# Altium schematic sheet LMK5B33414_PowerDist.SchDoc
size C; Date: Not shown in title block; ApprovedBy: Not shown in title block; CheckedBy: Not shown in title block; Author: Not shown in title block; CompanyName: Not shown in title block; Engineer: Not shown in title block; Organization: Not shown in title block; Address1: Not shown in title block; Address2: Not shown in title block; Address3: Not shown in title block; Address4: Not shown in title block; DocumentNumber: 2; Revision: Use project parameter SCH_Rev; SheetNumber: 2; SheetTotal: 3; PageSetup: Record=PageOptions¦CenterHorizontal=True¦CenterVertical=True¦PrintScale=1.00¦XCorrection=1.00¦YCorrection=1.00¦PrintKind=0¦BorderSize=5000000¦LeftOffset=0¦BottomOffset=0¦Orientation=2¦PaperLength=1000¦PaperWidth=1000¦Scale=100¦PaperSource=15¦PrintQuality=600¦MediaType=1¦DitherType=10¦PaperKind=Letter¦PrintScaleMode=1
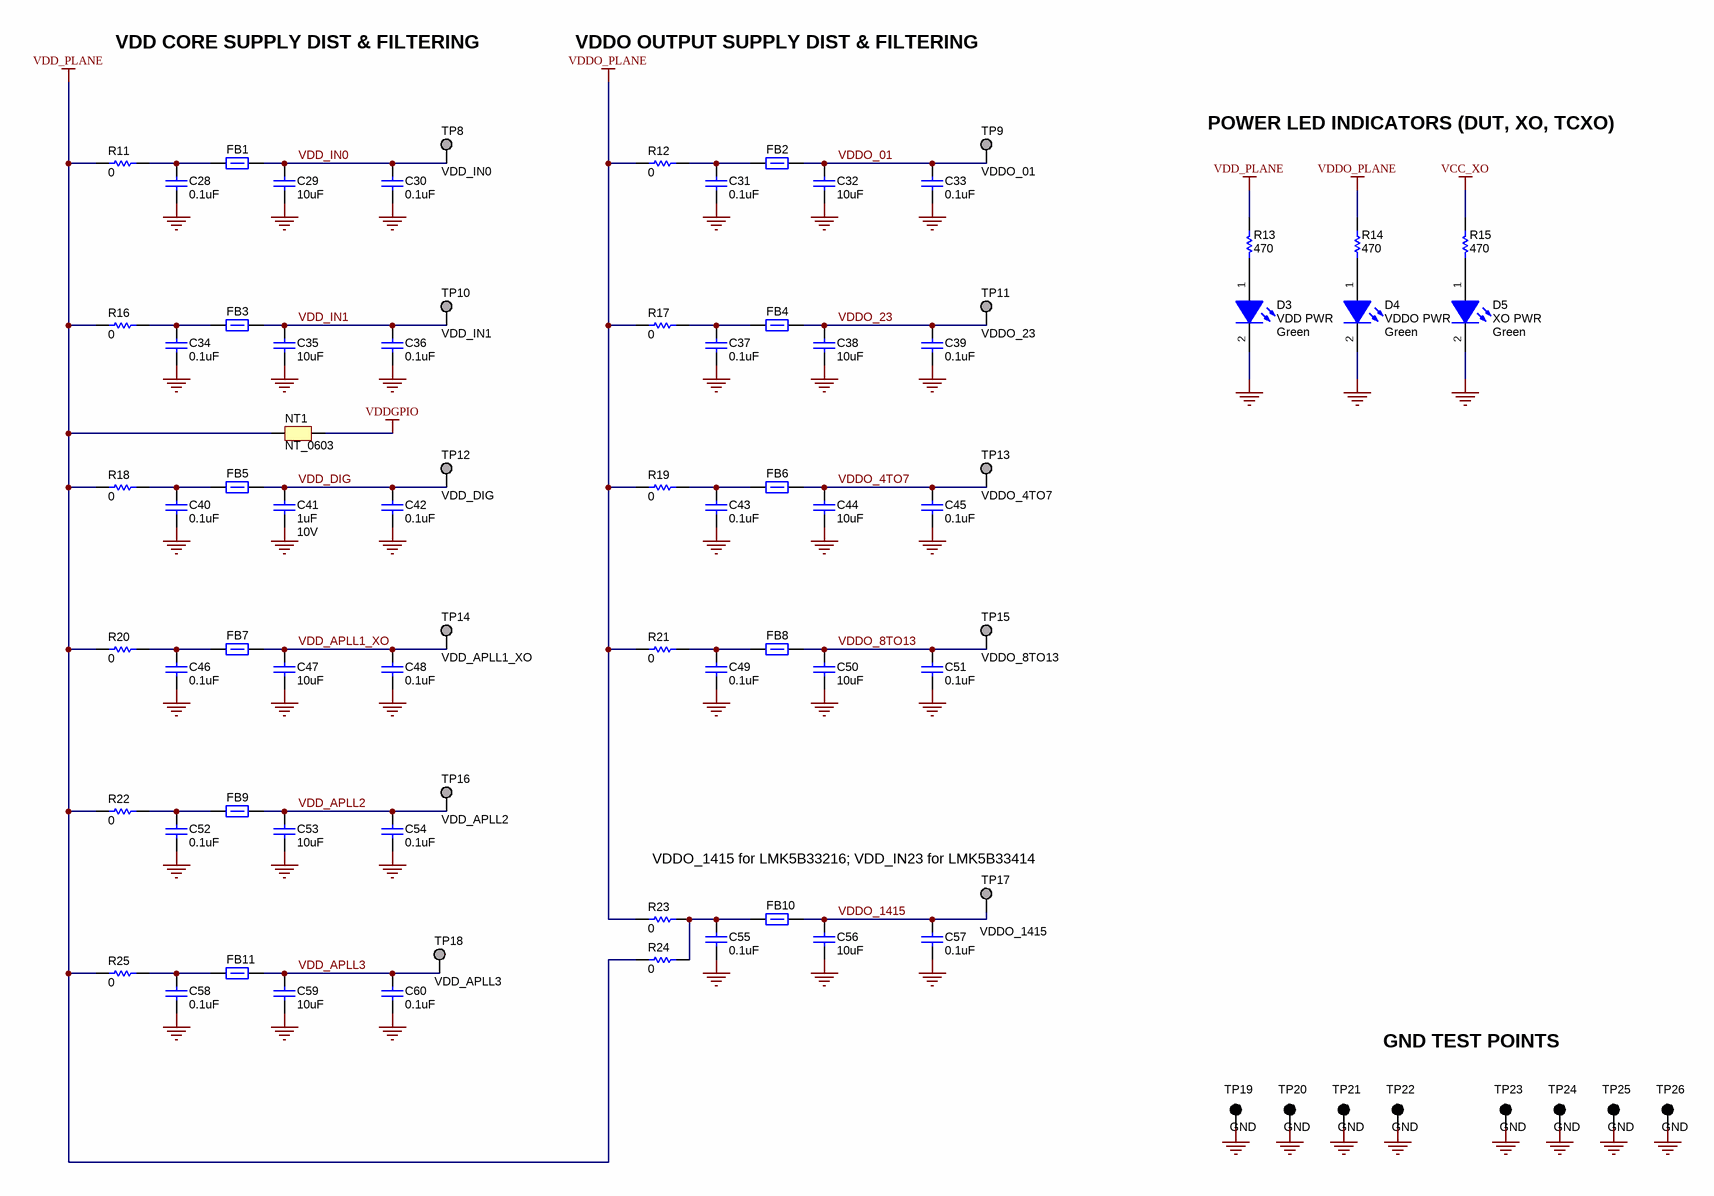
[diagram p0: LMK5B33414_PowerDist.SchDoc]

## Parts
C28  ValueDisplayed: 0.1uF  [0603L]  (hidden comment: Capacitor)
C29  ValueDisplayed: 10uF  [0603L]  (hidden comment: Capacitor)
C30  ValueDisplayed: 0.1uF  [0402L]  (hidden comment: Capacitor)
C31  ValueDisplayed: 0.1uF  [0603L]  (hidden comment: Capacitor)
C32  ValueDisplayed: 10uF  [0603L]  (hidden comment: Capacitor)
C33  ValueDisplayed: 0.1uF  [0402L]  (hidden comment: Capacitor)
C34  ValueDisplayed: 0.1uF  [0603L]  (hidden comment: Capacitor)
C35  ValueDisplayed: 10uF  [0603L]  (hidden comment: Capacitor)
C36  ValueDisplayed: 0.1uF  [0402L]  (hidden comment: Capacitor)
C37  ValueDisplayed: 0.1uF  [0603L]  (hidden comment: Capacitor)
C38  ValueDisplayed: 10uF  [0603L]  (hidden comment: Capacitor)
C39  ValueDisplayed: 0.1uF  [0402L]  (hidden comment: Capacitor)
C40  ValueDisplayed: 0.1uF  [0603L]  (hidden comment: Capacitor)
C41  ValueDisplayed: 1uF  VDC_V: 10V  [0603L]  (hidden comment: C0603C105K8PACTU)
C42  ValueDisplayed: 0.1uF  [0402L]  (hidden comment: Capacitor)
C43  ValueDisplayed: 0.1uF  [0603L]  (hidden comment: Capacitor)
C44  ValueDisplayed: 10uF  [0603L]  (hidden comment: Capacitor)
C45  ValueDisplayed: 0.1uF  [0402L]  (hidden comment: Capacitor)
C46  ValueDisplayed: 0.1uF  [0603L]  (hidden comment: Capacitor)
C47  ValueDisplayed: 10uF  [0603L]  (hidden comment: Capacitor)
C48  ValueDisplayed: 0.1uF  [0402L]  (hidden comment: Capacitor)
C49  ValueDisplayed: 0.1uF  [0603L]  (hidden comment: Capacitor)
C50  ValueDisplayed: 10uF  [0603L]  (hidden comment: Capacitor)
C51  ValueDisplayed: 0.1uF  [0402L]  (hidden comment: Capacitor)
C52  ValueDisplayed: 0.1uF  [0603L]  (hidden comment: Capacitor)
C53  ValueDisplayed: 10uF  [0603L]  (hidden comment: Capacitor)
C54  ValueDisplayed: 0.1uF  [0402L]  (hidden comment: Capacitor)
C55  ValueDisplayed: 0.1uF  [0603L]  (hidden comment: Capacitor)
C56  ValueDisplayed: 10uF  [0603L]  (hidden comment: Capacitor)
C57  ValueDisplayed: 0.1uF  [0402L]  (hidden comment: Capacitor)
C58  ValueDisplayed: 0.1uF  [0603L]  (hidden comment: Capacitor)
C59  ValueDisplayed: 10uF  [0603L]  (hidden comment: Capacitor)
C60  ValueDisplayed: 0.1uF  [0402L]  (hidden comment: Capacitor)
D3  VDD PWR  value Green  [LED_LTST-C190]
D4  VDDO PWR  value Green  [LED_LTST-C190]
D5  XO PWR  value Green  [LED_LTST-C190]
FB1  BLM18SG221TN1D  [0603L]  (value not drawn)
FB2  BLM18SG221TN1D  [0603L]  (value not drawn)
FB3  BLM18SG221TN1D  [0603L]  (value not drawn)
FB4  BLM18SG221TN1D  [0603L]  (value not drawn)
FB5  BLM18SG221TN1D  [0603L]  (value not drawn)
FB6  BLM18SG221TN1D  [0603L]  (value not drawn)
FB7  BLM18SG221TN1D  [0603L]  (value not drawn)
FB8  BLM18SG221TN1D  [0603L]  (value not drawn)
FB9  BLM18SG221TN1D  [0603L]  (value not drawn)
FB10  BLM18SG221TN1D  [0603L]  (value not drawn)
FB11  BLM18SG221TN1D  [0603L]  (value not drawn)
NT1  NT_0603  [NetTie_0603]  (net tie, no BOM)
R11  ValueDisplayed: 0  [0603]  (hidden comment: CRCW06030000Z0EA)
R12  ValueDisplayed: 0  [0603]  (hidden comment: CRCW06030000Z0EA)
R13  ValueDisplayed: 470  [0603]  (hidden comment: Resistor)
R14  ValueDisplayed: 470  [0603]  (hidden comment: Resistor)
R15  ValueDisplayed: 470  [0603]  (hidden comment: Resistor)
R16  ValueDisplayed: 0  [0603]  (hidden comment: CRCW06030000Z0EA)
R17  ValueDisplayed: 0  [0603]  (hidden comment: CRCW06030000Z0EA)
R18  ValueDisplayed: 0  [0603]  (hidden comment: CRCW06030000Z0EA)
R19  ValueDisplayed: 0  [0603]  (hidden comment: CRCW06030000Z0EA)
R20  ValueDisplayed: 0  [0603]  (hidden comment: CRCW06030000Z0EA)
R21  ValueDisplayed: 0  [0603]  (hidden comment: CRCW06030000Z0EA)
R22  ValueDisplayed: 0  [0603]  (hidden comment: CRCW06030000Z0EA)
R23  ValueDisplayed: 0  [0603]  (hidden comment: CRCW06030000Z0EA)
R24  ValueDisplayed: 0  [0603]  (hidden comment: CRCW06030000Z0EA)
R25  ValueDisplayed: 0  [0603]  (hidden comment: CRCW06030000Z0EA)
TP8  VDD_IN0  [TP_SM_1MM]  (no BOM)
TP9  VDDO_01  [TP_SM_1MM]  (no BOM)
TP10  VDD_IN1  [TP_SM_1MM]  (no BOM)
TP11  VDDO_23  [TP_SM_1MM]  (no BOM)
TP12  VDD_DIG  [TP_SM_1MM]  (no BOM)
TP13  VDDO_4TO7  [TP_SM_1MM]  (no BOM)
TP14  VDD_APLL1_XO  [TP_SM_1MM]  (no BOM)
TP15  VDDO_8TO13  [TP_SM_1MM]  (no BOM)
TP16  VDD_APLL2  [TP_SM_1MM]  (no BOM)
TP17  VDDO_1415  [TP_SM_1MM]  (no BOM)
TP18  VDD_APLL3  [TP_SM_1MM]  (no BOM)
TP19  GND  [Keystone5001]
TP20  GND  [Keystone5001]
TP21  GND  [Keystone5001]
TP22  GND  [Keystone5001]
TP23  GND  [Keystone5001]
TP24  GND  [Keystone5001]
TP25  GND  [Keystone5001]
TP26  GND  [Keystone5001]

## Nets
GND: C28.1 C29.2 C30.1 C31.1 C32.2 C33.1 C34.1 C35.2 C36.1 C37.1 C38.2 C39.1 C40.1 C41.2 C42.1 C43.1 C44.2 C45.1 C46.1 C47.2 C48.1 C49.1 C50.2 C51.1 C52.1 C53.2 C54.1 C55.1 C56.2 C57.1 C58.1 C59.2 C60.1 D3.2(K) D4.2(K) D5.2(K) TP19.1 TP20.1 TP21.1 TP22.1 TP23.1 TP24.1 TP25.1 TP26.1
VCC_XO: R15.1
VDD_PLANE: NT1.2 R11.2 R13.1 R16.2 R18.2 R20.2 R22.2 R24.1 R25.2
VDDGPIO: NT1.1
VDDO_PLANE: R12.2 R14.1 R17.2 R19.2 R21.2 R23.2
VDD_APLL1_XO: C47.1 C48.2 FB7.2 TP14.1
VDD_APLL2: C53.1 C54.2 FB9.2 TP16.1
VDD_APLL3: C59.1 C60.2 FB11.2 TP18.1
VDD_DIG: C41.1 C42.2 FB5.2 TP12.1
VDD_IN0: C29.1 C30.2 FB1.2 TP8.1
VDD_IN1: C35.1 C36.2 FB3.2 TP10.1
VDDO_01: C32.1 C33.2 FB2.2 TP9.1
VDDO_4TO7: C44.1 C45.2 FB6.2 TP13.1
VDDO_8TO13: C50.1 C51.2 FB8.2 TP15.1
VDDO_23: C38.1 C39.2 FB4.2 TP11.1
VDDO_1415: C56.1 C57.2 FB10.2 TP17.1
NetC28_2: C28.2 FB1.1 R11.1
NetC31_2: C31.2 FB2.1 R12.1
NetC34_2: C34.2 FB3.1 R16.1
NetC37_2: C37.2 FB4.1 R17.1
NetC40_2: C40.2 FB5.1 R18.1
NetC43_2: C43.2 FB6.1 R19.1
NetC46_2: C46.2 FB7.1 R20.1
NetC49_2: C49.2 FB8.1 R21.1
NetC52_2: C52.2 FB9.1 R22.1
NetC55_2: C55.2 FB10.1 R23.1 R24.2
NetC58_2: C58.2 FB11.1 R25.1
NetD3_1: D3.1(A) R13.2
NetD4_1: D4.1(A) R14.2
NetD5_1: D5.1(A) R15.2

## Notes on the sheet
- VDD CORE SUPPLY DIST & FILTERING
- VDDO OUTPUT SUPPLY DIST & FILTERING
- POWER LED INDICATORS (DUT, XO, TCXO)
- VDDO_1415 for LMK5B33216; VDD_IN23 for LMK5B33414
- GND TEST POINTS

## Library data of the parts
C28 C31 C34 C37 C40 C43 C46 C49 C52 C55 C58 = CMP-0006856-6: CAP, CERM, 0.1 uF, 25 V, +/- 5%, X7R, 0603; PartNumber: C0603C104J3RACTU; Manufacturer: Kemet; Polarized: N; Value: 0.1uF; U/M: EA; Cap_F: 100nF; Value1: Unknown; VDC_V: 25V; TaMin_C: -55°C; TaMax_C: 125°C; Cap_Case: 0603; AEC Category: Q200; SizeArea_mm2: 1.28; SizeAreaWB_mm2: 4.68; SizeX_mm: 1.6; SizeY_mm: 0.8; SizeZ_mm: 1
C29 C32 C35 C38 C44 C47 C50 C53 C56 C59 = CMP-0007003-5: CAP, CERM, 10 uF, 10 V, +/- 20%, X5R, 0603; PartNumber: C1608X5R1A106M080AC; Manufacturer: TDK; Polarized: N; Value: 10uF; U/M: EA; Cap_F: 10µF; ESR_ohm: 7.8m; Value1: 0.0078 ohm; VDC_V: 10V; IRMS_A: 1.85A; TaMin_C: -55°C; TaMax_C: 85°C; Cap_Case: 0603; SizeArea_mm2: 1.28; SizeAreaWB_mm2: 4.68; SizeX_mm: 1.6; SizeY_mm: 0.8; SizeZ_mm: 1; AEC Category: Q200
C30 C33 C36 C39 C42 C45 C48 C51 C54 C57 C60 = CMP-0006259-2: CAP, CERM, 0.1 uF, 10 V, +/- 10%, X5R, 0402; PartNumber: C1005X5R1A104K050BA; Manufacturer: TDK; Polarized: N; Value: 0.1uF; U/M: EA; Cap_F: 100nF; Value1: Unknown; VDC_V: 10V; TaMin_C: -55°C; TaMax_C: 85°C; Cap_Case: 0402; SizeArea_mm2: 0.5; SizeAreaWB_mm2: 3; SizeX_mm: 1; SizeZ_mm: 0.6; AEC Category: Q200
C41 = CMP-0006869-5: CAP, CERM, 1 uF, 10 V, +/- 10%, X5R, 0603; Manufacturer: Kemet; Polarized: N; Value: 1uF; U/M: EA; Cap_F: 1µF; Value1: Unknown; TaMin_C: -55°C; TaMax_C: 85°C; Cap_Case: 0603; SizeArea_mm2: 1.28; SizeAreaWB_mm2: 4.68; SizeX_mm: 1.6; SizeY_mm: 0.8; SizeZ_mm: 1; AEC Category: Q200
D3-D5 = CMP-0002827-3: LED, Green, SMD; Manufacturer: Lite-On; PartNumber: LTST-C190GKT; Vf_V: 2.1V; Io_A: 20mA; Power_TotalModule: 100mW; Value1: 0.1W
FB1-FB11 = CMP-0003353-2: Ferrite Bead, 220 ohm @ 100 MHz, 2.5 A, 0603; Manufacturer: MuRata; Value: 220 ohm; Imax_A: 2.5A; DCR_ohm: 0.04; Value1: 0.04 ohm; ZTyp@100MHz_Ohm: 220; SizeArea_mm2: 1.28; SizeAreaWB_mm2: 4.68; SizeX_mm: 1.6; SizeY_mm: 0.8; SizeZ_mm: 1
NT1 = CMP-0078142-3: Single point connection between nets.
R11 R12 R16-R25 = CMP-0025697-4: RES, 0, 5%, 0.1 W, AEC-Q200 Grade 0, 0603; Manufacturer: Vishay-Dale; Power_W: 100mW; TempCo: 200 ppm/C; Value_Code: 0000; Value: 0; EIA_Code: E24; SizeX_mm: 1.6; SizeY_mm: 0.8; SizeZ_mm: 1; Value2: 0.1W; SizeArea_mm2: 1.28; AEC Qualified: Y; VDC_V: 75V; AEC Category: Q200
R13-R15 = CMP-0025813-4: RES, 470, 5%, 0.1 W, AEC-Q200 Grade 0, 0603; PartNumber: CRCW0603470RJNEA; Manufacturer: Vishay-Dale; Value: 470; Value_Code: 470R; Power_W: 100mW; Value2: 0.1W; VDC_V: 75V; TempCo: 200 ppm/C; EIA_Code: E24; SizeArea_mm2: 1.28; SizeX_mm: 1.6; SizeY_mm: 0.8; SizeZ_mm: 1; AEC Category: Q200; AEC Qualified: Y; AEC Grade: 0
TP8-TP18 = CMP-0003825-1: 1mm Test Point, SMT; Manufacturer: Any
TP19-TP26 = CMP-0055138-1: Test Point, Miniature, Black, TH; Manufacturer: Keystone; ContactFinish: Silver; CNHeader: FALSE; CT: TRUE; Green_Lifecycle: Active; Green_REACh: Passed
